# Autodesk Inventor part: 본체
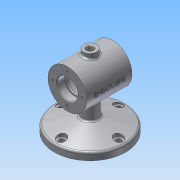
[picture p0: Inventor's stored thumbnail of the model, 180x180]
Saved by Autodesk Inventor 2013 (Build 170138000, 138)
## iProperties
Created: 2018-12
Part Number: 본체
Material: 알루미늄 6061
Document SubType Name: Modeling
Designer: Administrator
Mass: 687.651 g
Surface Area: 556.954 cm^2
Volume: 253.746 cm^3
Density: 2.71 g/cm^3
Author: Administrator
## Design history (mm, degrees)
sketch "스케치1"
  geometry: C1 r 30 at (0, 0); 1 further point
  constraints: 1 centre point, 1 coincident
  dimensions: "d0" = 60 diameter of C1
extrude "돌출1" new body sketch "스케치1" stored distance "d2" = 70; taper "d3" = 0 deg
sketch "스케치2" dims "d4" = 46
  geometry: L1 (0, 0)-(0, 23); C1 r 30 at (0, 0) reference
  constraints: 2 end point, 1 coincident, 1 vertical, 1 vertical alignment, 2 other
hole "구멍1" sketch "스케치2" at (0, 23) diameter "d6" = 3.242; stored, may be unused: countersink angle "d10" = 90 deg, drill point angle "d12" = 118 deg; dims "d7" = 8, "d8" = 4, "d9" = 2, "d11" = 10
sketch "스케치3"
  geometry: C1 r 30 at (0, 0) reference; C2 r 16 at (0, 0)
  constraints: 1 centre point, 1 coincident
  dimensions: "d16" = 32 diameter of C2
extrude "돌출2" cut sketch "스케치3" distance "d18" = 12; taper "d19" = 0 deg
hole "구멍2" diameter "d22" = 28; stored, may be unused: countersink angle "d26" = 90 deg, drill point angle "d28" = 0 deg; dims "d20" = 10, "d21" = 10, "d23" = 8, "d24" = 4, "d25" = 2, "d27" = 3
hole "구멍3" diameter "d31" = 50; stored, may be unused: countersink angle "d35" = 90 deg, drill point angle "d37" = 0 deg; dims "d29" = 10, "d30" = 10, "d32" = 8, "d33" = 4, "d34" = 2, "d36" = 40
hole "구멍4" diameter "d40" = 28; stored, may be unused: countersink angle "d44" = 90 deg, drill point angle "d46" = 0 deg; dims "d38" = 10, "d39" = 10, "d41" = 8, "d42" = 4, "d43" = 2, "d45" = 3
hole "구멍5" diameter "d49" = 32; stored, may be unused: countersink angle "d53" = 90 deg, drill point angle "d55" = 0 deg; dims "d47" = 10, "d48" = 10, "d50" = 8, "d51" = 4, "d52" = 2, "d54" = 12
node "작업 평면1"
sketch "스케치4"
  geometry: L1 (-30, -35)-(30, -35) reference; L2 (30, 35)-(-30, 35) reference; C1 r 10 at (0, 0); 1 further point
  constraints: 1 centre point, 1 coincident
  dimensions: "d58" = 20 diameter of C1
extrude "돌출3" join sketch "스케치4" stored distance "d60" = 12; taper "d61" = 0 deg
sketch "스케치5"
  geometry: C1 r 10 at (0, 0) reference; C2 r 5 at (0, 0)
  constraints: 1 centre point, 1 coincident
  dimensions: "d62" = 10 diameter of C2
extrude "돌출4" cut sketch "스케치5" distance "d64" = 12; taper "d65" = 0 deg
fillet "모깎기1" dims "d66" = 3
chamfer "모따기1" distance "d67" = 1; stored, may be unused: second distance "d68" = 2, angle "d69" = 45 deg
chamfer "모따기2" distance "d70" = 1; stored, may be unused: second distance "d71" = 2, angle "d72" = 45 deg
fillet "모깎기2" dims "d73" = 3
fillet "모깎기3" dims "d74" = 0.3
node "작업 평면2"
sketch "스케치6"
  geometry: L1 (-30, -35)-(30, -35) reference; L2 (30, 35)-(-30, 35) reference; C1 r 55 at (0, 0); 2 further points
  constraints: 1 centre point, 1 coincident, 1 other
  dimensions: "d76" = 110 diameter of C1
extrude "돌출5" join sketch "스케치6" distance "d78" = 11; taper "d79" = 0 deg
sketch "스케치7"
  geometry: L1 (55, -64)-(-55, -64) reference; L2 (0, -64)-(0, -30); L3 (12, -52.478)-(12, -27.495); L4 (55, -75)-(55, -64) reference; L5 (55, -64)-(12, -52.478); L6 (55, -64)-(0, -64); A1 r 30 centre (0, 0) between (0, -30) and (12, -27.495) reference; A2 r 30 centre (0, 0) between (0, -30) and (12, -27.495); 1 further point
  constraints: 8 end point, 4 point on circle, 1 centre point, 1 coincident, 1 collinear, 1 midpoint, 1 parallel, 1 perpendicular
  dimensions: "d80" = 12 distance between parallel lines of L3 L2; "d82" = 75 deg angle of L4 L5
revolve "회전1" sketch "스케치7" stored, may be unused: angle "d84" = 90 deg
sketch "스케치8" dims "d85" = 88
  geometry: L1 (0, 0)-(0, 44); C1 r 55 at (0, 0) reference; C2 r 4.5 at (0, 44)
  constraints: 2 coincident, 2 end point, 1 centre point, 1 vertical, 1 vertical alignment, 2 other
  dimensions: "d87" = 9 diameter of C2
extrude "돌출6" cut sketch "스케치8" distance "d88" = 10; taper "d89" = 0 deg
node "작업 평면3"
sketch "스케치9" dims "d94" = 88
  geometry: L1 (0, 0)-(0, 44); C1 r 7 at (0, 44); 1 further point
  constraints: 2 coincident, 2 end point, 1 centre point, 1 vertical, 1 vertical alignment, 2 other
  dimensions: "d96" = 14 diameter of C1
extrude "돌출7" cut sketch "스케치9" distance "d97" = 10; taper "d98" = 0 deg
node "작업 평면4"
sketch "스케치10"
  geometry: L1 (30, 35)-(-30, 35) reference; L2 (30, -35)-(30, 35) reference; 2 further points
  constraints: 1 other
  dimensions: "d103" = 35 distance from line of point (0, 0) L1; "d104" = 30 distance from line of point (0, 0) L2
feature "엠보싱1" sketch "스케치10" dims "d105" = 0.5, "d106" = 0
fillet "모깎기4" dims "d107" = 3
node "솔리드1"
pattern_circular "원형 패턴1" dims angle "d14" = 360 deg
mirror "대칭1"
pattern_circular "원형 패턴2" dims angle "d91" = 360 deg
pattern_circular "원형 패턴3" dims angle "d100" = 360 deg
node "투영된 루프1"
node "투영된 루프2"
other parameters: "d56" = 37, "d75" = -75, "d102" = 39.5
